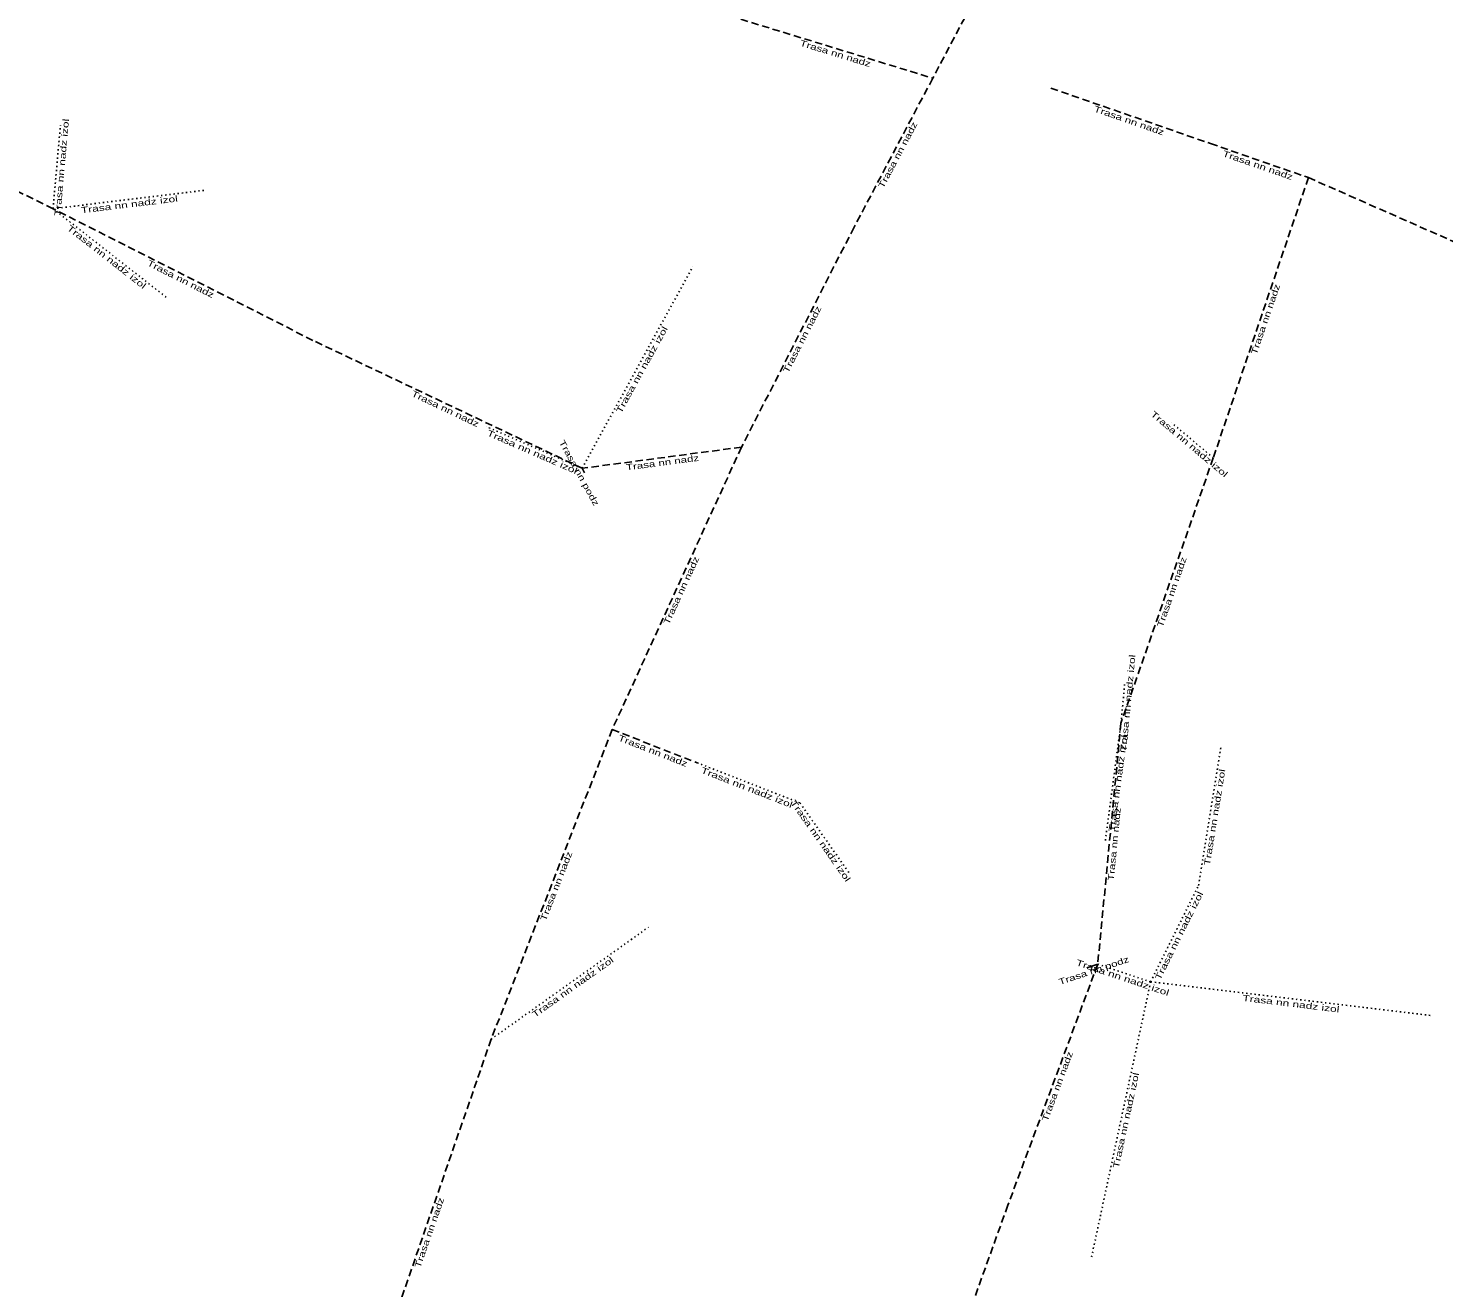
# Model space of a CAD drawing. Extents: x -733620 to -732615, y -1025255 to -1024617.
# Drawn here: x -733024.6 to -732909.6, y -1024970.5 to -1024868.1 of the extents above; entities that cross this region are included whole.
import ezdxf
from ezdxf.enums import TextEntityAlignment as Align

# ---------------------------------------------------------------- set-up
doc = ezdxf.new("R2010")
doc.units = 0
doc.header["$LTSCALE"] = 0.2
doc.linetypes.add('DOTTED', pattern=[1.5, 0.3, -1.2])
doc.linetypes.add('MEDIUM_DASHED', pattern=[4.5, 3, -1.5])
doc.layers.add('11', color=7, linetype='MEDIUM_DASHED', lineweight=25)
doc.layers.add('20', color=7, linetype='Continuous')

msp = doc.modelspace()

# ---------------------------------------------------------------- linework, layer by layer
at = {"layer": '11'}
for p, q in [((-732933.38, -1024838.62), (-732951.106, -1024872.192)), ((-732966.7, -1024867.4), (-732951.11, -1024872.19)), ((-732951.106, -1024872.192), (-732957.5, -1024884.3)), ((-732941.5, -1024873), (-732928.544, -1024877.502)), ((-733022.6, -1024882.8), (-733035.676, -1024876.348)), ((-732928.544, -1024877.502), (-732920.58, -1024880.27)), ((-732920.58, -1024880.27), (-732928.31, -1024903.05)), ((-732920.58, -1024880.27), (-732890.1, -1024893.7)), ((-733001.5, -1024893.5), (-733022.6, -1024882.8)), ((-732957.5, -1024884.3), (-732966.65, -1024902.18)), ((-732979.6, -1024903.9), (-733001.5, -1024893.5)), ((-732966.65, -1024902.18), (-732979.6, -1024903.9)), ((-732966.65, -1024902.18), (-732977.16, -1024925.14)), ((-732928.31, -1024903.05), (-732935.81, -1024924.61)), ((-732935.81, -1024924.61), (-732937.7, -1024944.2)), ((-732977.16, -1024925.14), (-732986.99, -1024950.3)), ((-732977.16, -1024925.14), (-732970.246, -1024927.84)), ((-732937.7, -1024944.2), (-732945, -1024963.8)), ((-732986.99, -1024950.3), (-732997.8, -1024981.5)), ((-732945, -1024963.8), (-732953.11, -1024986.33))]:
    msp.add_line(p, q, dxfattribs=at)
at = {"layer": '11', "linetype": 'DOTTED'}
for p, q in [((-733022.6, -1024882.8), (-733022, -1024876)), ((-733022.6, -1024882.8), (-733010.3, -1024881.3)), ((-733022.6, -1024882.8), (-733013.4, -1024890)), ((-732979.6, -1024903.9), (-732970.6, -1024887.5)), ((-732979.6, -1024903.9), (-732987.4, -1024900.5)), ((-732928.31, -1024903.05), (-732931.7, -1024900.2)), ((-732935.81, -1024924.61), (-732935.5, -1024921.3)), ((-732935.81, -1024924.61), (-732937.1, -1024934.3)), ((-732929.5, -1024937.8), (-732927.7, -1024926.6)), ((-732970.246, -1024927.84), (-732961.9, -1024931.1)), ((-732961.9, -1024931.1), (-732957.9, -1024936.8)), ((-732933.4, -1024945.64), (-732929.5, -1024937.8)), ((-732986.99, -1024950.3), (-732974.2, -1024941.2)), ((-732937.7, -1024944.2), (-732933.4, -1024945.64)), ((-732933.4, -1024945.64), (-732938.2, -1024968)), ((-732933.4, -1024945.64), (-732910.5, -1024948.4))]:
    msp.add_line(p, q, dxfattribs=at)
at = {"layer": '11', "linetype": 'Continuous'}
for p, q in [((-732979.6, -1024903.9), (-732979.398, -1024904.268)), ((-732937.7, -1024944.2), (-732938.6, -1024944.5))]:
    msp.add_line(p, q, dxfattribs=at)

# ---------------------------------------------------------------- texts
at = {"layer": '20'}
for s, rotation, width, p in [('Trasa nn nadz', 342.921, 1.4, (-732959.0949, -1024870.4153)), ('Trasa nn nadz', 340.838, 1.4, (-732935.2346, -1024875.8648)), ('Trasa nn nadz izol', 84.958, 1.45, (-733021.6527, -1024879.4565)), ('Trasa nn nadz', 62.165, 1.4, (-732953.7282, -1024878.5492)), ('Trasa nn nadz', 340.834, 1.4, (-732924.7746, -1024879.5001)), ('Trasa nn nadz izol', 6.953, 1.45, (-733016.3718, -1024882.6944)), ('Trasa nn nadz izol', 321.953, 1.45, (-733018.4006, -1024886.9119)), ('Trasa nn nadz', 333.11, 1.4, (-733012.3436, -1024888.7296)), ('Trasa nn nadz', 71.256, 1.4, (-732923.8287, -1024891.8688)), ('Trasa nn nadz', 62.899, 1.4, (-732961.4958, -1024893.5354)), ('Trasa nn nadz izol', 61.243, 1.45, (-732974.5289, -1024896.0118)), ('Trasa nn nadz', 334.598, 1.4, (-732990.8287, -1024899.2863)), ('Trasa nn nadz izol', 319.946, 1.45, (-732930.4224, -1024902.1221)), ('Trasa nn nadz izol', 336.448, 1.45, (-732983.7594, -1024902.7957)), ('Trasa nn podz', 298.806, 1.4, (-732980.0676, -1024904.396)), ('Trasa nn nadz', 7.566, 1.4, (-732973.0384, -1024903.6841)), ('Trasa nn nadz', 65.404, 1.4, (-732971.3135, -1024913.9296)), ('Trasa nn nadz', 70.819, 1.4, (-732931.4451, -1024914.0426)), ('Trasa nn nadz izol', 84.65, 1.45, (-732935.0073, -1024923.0148)), ('Trasa nn nadz', 338.666, 1.4, (-732973.9394, -1024927.0958)), ('Trasa nn nadz izol', 82.417, 1.45, (-732935.8095, -1024929.5405)), ('Trasa nn nadz izol', 338.666, 1.45, (-732966.3095, -1024930.0759)), ('Trasa nn nadz izol', 80.87, 1.45, (-732927.9575, -1024932.3022)), ('Trasa nn nadz izol', 305.059, 1.45, (-732960.4312, -1024934.3229)), ('Trasa nn nadz', 84.489, 1.4, (-732936.1081, -1024934.4665)), ('Trasa nn nadz', 68.659, 1.4, (-732981.4692, -1024937.9565)), ('Trasa nn nadz izol', 63.552, 1.45, (-732930.8674, -1024942.0088)), ('Trasa nn nadz izol', 35.432, 1.45, (-732980.2174, -1024946.2799)), ('Trasa nn podz', 18.435, 1.4, (-732937.9446, -1024944.9659)), ('Trasa nn nadz izol', 341.485, 1.45, (-732935.7559, -1024945.5361)), ('Trasa nn nadz izol', 353.128, 1.45, (-732922.0274, -1024947.6646)), ('Trasa nn nadz', 69.572, 1.4, (-732940.7397, -1024954.2268)), ('Trasa nn nadz izol', 77.884, 1.45, (-732935.1639, -1024956.956)), ('Trasa nn nadz', 70.89, 1.4, (-732991.7797, -1024966.1123))]:
    msp.add_text(s, height=0.5, rotation=rotation, dxfattribs=dict(at, width=width)).set_placement(p, align=Align.CENTER)

doc.saveas('drawing.dxf')
